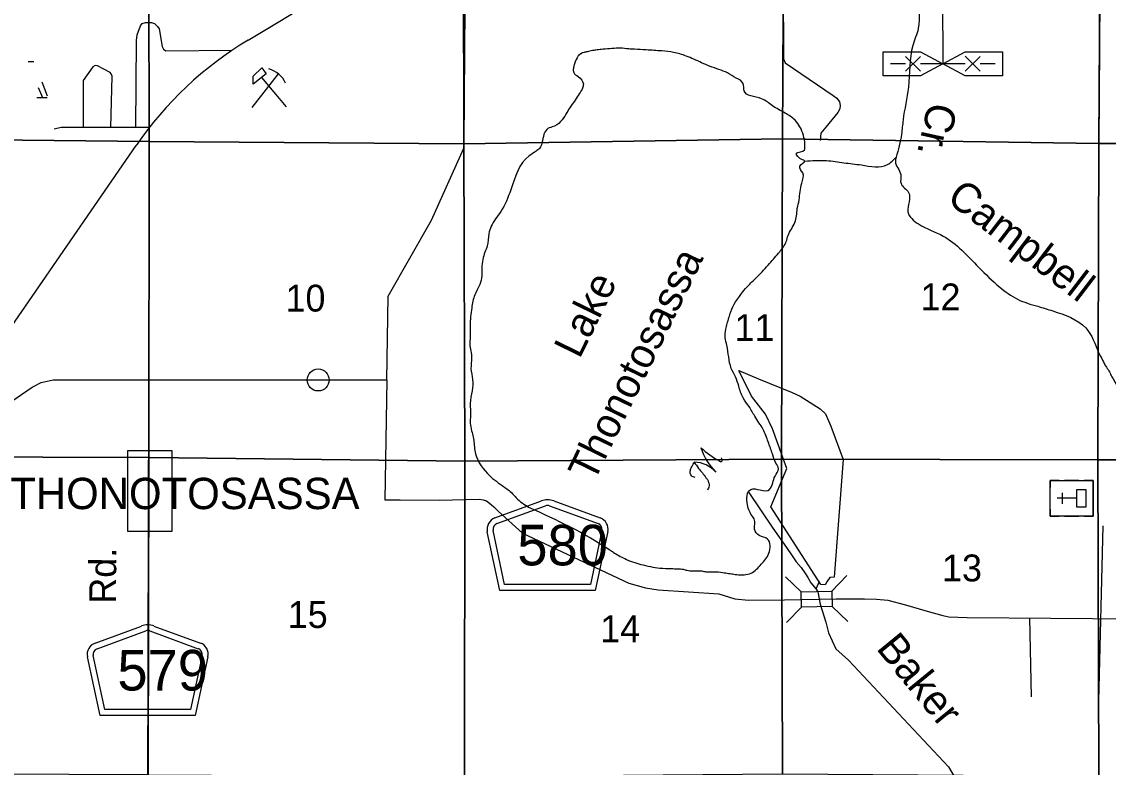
# Model space of a CAD drawing. Extents: x 380424 to 701066, y 1117407 to 1412949.
# Drawn here: x 556420 to 574618, y 1347425 to 1359908 of the extents above; entities that cross this region are included whole.
import ezdxf

# ---------------------------------------------------------------- set-up
doc = ezdxf.new("R2010")
doc.units = 0
for name, color, linetype in [('Bridges and Drawbridges County Highways', 7, 'Continuous'), ('Communities Names with Post Office', 7, 'Continuous'), ('County Roads Related Text', 7, 'Continuous'), ('County Routes Highway Center Lines', 7, 'Continuous'), ('Culture', 7, 'Continuous'), ('Lakes and Ponds', 7, 'Continuous'), ('Lakes and Ponds Text', 7, 'Continuous'), ('Local Roads Improved', 7, 'Continuous'), ('Local Roads Paved', 7, 'Continuous'), ('Local Roads Related Cells', 7, 'Continuous'), ('Masks for Text', 7, 'Continuous'), ('Narrow Canals', 7, 'Continuous'), ('Narrow River Creek and Branch and Slough', 7, 'Continuous'), ('Narrow River Creek and Branch and Slough Text', 7, 'Continuous'), ('Roadshields County Roads', 7, 'Continuous'), ('Section Lines', 7, 'Continuous'), ('Section Numbers', 7, 'Continuous'), ('Swamps', 7, 'Continuous'), ('Town Centers', 7, 'Continuous'), ('Township  and Range lines', 7, 'Continuous'), ('US Routes Highway Center Lines', 7, 'Continuous'), ('Wide Rivers and Canals Text', 7, 'Continuous')]:
    doc.layers.add(name, color=color, linetype=linetype)

msp = doc.modelspace()

# ---------------------------------------------------------------- linework, layer by layer
at = {"layer": 'Bridges and Drawbridges County Highways'}
for p, q in [((569475, 1350364), (569213, 1350614)), ((569986, 1350374), (570237, 1350635)), ((569992, 1350118), (570253, 1349867)), ((569480, 1350108), (569229, 1349847))]:
    msp.add_line(p, q, dxfattribs=at)
msp.add_lwpolyline([(569475, 1350364), (569986, 1350374), (569992, 1350118), (569480, 1350108)], close=True, dxfattribs=at)
at = {"layer": 'County Routes Highway Center Lines'}
msp.add_line((558555, 1358137), (558465, 1326167), dxfattribs=at)
msp.add_lwpolyline([(562533, 1353909), (562500, 1351905), (562760, 1351905), (563413, 1351899), (564087, 1351912), (564146, 1351902), (564203, 1351884), (564254, 1351846), (564290, 1351821), (564327, 1351786), (564401, 1351713), (564804, 1351342), (566590, 1350510), (566869, 1350431), (567079, 1350396), (568093, 1350326), (568364, 1350247), (568592, 1350221), (569195, 1350230), (570060, 1350247), (570533, 1350247), (570734, 1350239), (570926, 1350221), (571223, 1350142), (571582, 1350037), (571844, 1349967), (571949, 1349941), (572255, 1349932), (577859, 1349889)], dxfattribs=at)
at = {"layer": 'Culture'}
for p, q in [((560281, 1358474), (560718, 1359033)), ((560438, 1358975), (560851, 1358482)), ((573643, 1352228), (573643, 1352108)), ((573793, 1352228), (573643, 1352228)), ((574123, 1352228), (573883, 1352228)), ((574363, 1352228), (574213, 1352228)), ((574363, 1351628), (574363, 1352228)), ((573643, 1351838), (573643, 1352018)), ((573853, 1351838), (573853, 1352018)), ((574093, 1351928), (573763, 1351928)), ((573643, 1351748), (573643, 1351628)), ((573643, 1351628), (573793, 1351628)), ((573883, 1351628), (574123, 1351628)), ((574213, 1351628), (574363, 1351628))]:
    msp.add_line(p, q, dxfattribs=at)
for points in [[(560443, 1359134), (560513, 1359035), (560298, 1358863), (560298, 1358998)], [(573643, 1351628), (573643, 1352228), (574363, 1352228), (574363, 1351628)], [(574093, 1351778), (574093, 1352078), (574243, 1352078), (574243, 1351778)]]:
    msp.add_lwpolyline(points, close=True, dxfattribs=at)
msp.add_arc((560447, 1358701), 431, 24.5404, 74.8293, dxfattribs=at)
at = {"layer": 'Lakes and Ponds'}
msp.add_line((569408, 1356779), (569408, 1356782), dxfattribs=at)
msp.add_lwpolyline([(568430, 1354069), (568758, 1353927), (569324, 1353702), (569459, 1353637), (569793, 1353425), (569883, 1353341), (569973, 1353136), (570179, 1352576), (570024, 1350609), (569954, 1350603), (569902, 1350532), (569877, 1350481), (569806, 1350487), (568964, 1351786), (569234, 1352429), (568996, 1353092), (568874, 1353336), (568642, 1353638)], close=True, dxfattribs=at)
for centre, radius, start, end in [((568775, 1353091), 1029, 197.8123, 224.9499), ((568866, 1353931), 1575, 227.1631, 241.0317), ((567675, 1352045), 489, 40.6586, 89.0894)]:
    msp.add_arc(centre, radius, start, end, dxfattribs=at)
for points in [[(569408, 1356782), (569439, 1356924), (569457, 1357063), (569485, 1357205), (569500, 1357380), (569451, 1357489), (569531, 1357581), (569494, 1357597), (569395, 1357705), (569531, 1357761), (569537, 1357816), (569536, 1357858), (569454, 1358146), (569372, 1358259), (569204, 1358378), (568993, 1358502), (568811, 1358619), (568518, 1358752), (568502, 1358876), (568388, 1358965), (568239, 1359052), (567949, 1359160), (567807, 1359222), (567547, 1359333), (567337, 1359395), (567142, 1359419), (566876, 1359435), (566682, 1359447), (566586, 1359453), (566444, 1359466), (566305, 1359460), (566156, 1359447), (566057, 1359435), (565980, 1359425), (565893, 1359405), (565838, 1359395), (565741, 1359335), (565679, 1359204), (565659, 1359124), (565665, 1359057), (565739, 1358990), (565826, 1358862), (565811, 1358793), (565757, 1358702), (565688, 1358596), (565594, 1358460), (565535, 1358362), (565445, 1358236), (565303, 1358146), (565255, 1358132), (565181, 1358058), (565091, 1357787), (565034, 1357739), (564916, 1357660), (564611, 1357092)], [(564611, 1357092), (564442, 1356728), (564281, 1356483), (564243, 1356356), (564215, 1356153), (564178, 1356052), (564141, 1355926), (564125, 1355783), (564120, 1355614), (564078, 1355477), (564009, 1355335), (563956, 1355118), (563930, 1354823), (563930, 1354621), (563924, 1354513), (563955, 1354277), (563943, 1354104), (563972, 1353915), (563962, 1353730), (563930, 1353514), (563936, 1353394), (563933, 1353187), (563955, 1353059), (563997, 1352848), (564009, 1352727), (564218, 1352345), (564467, 1352142), (564620, 1352024), (564702, 1351934), (564910, 1351780)], [(564910, 1351780), (566271, 1351063), (566326, 1351026), (566518, 1350918), (566790, 1350822), (567108, 1350760), (567300, 1350751), (567405, 1350748), (567495, 1350739), (567563, 1350723), (567658, 1350714), (567791, 1350714), (567865, 1350702), (567906, 1350698), (567952, 1350695), (567992, 1350698), (568060, 1350698), (568187, 1350683), (568283, 1350668), (568369, 1350655), (568394, 1350652), (568635, 1350674), (568805, 1350825), (568935, 1351008), (568910, 1351246), (568771, 1351308), (568694, 1351410), (568697, 1351490), (568686, 1351582), (568663, 1351619), (568573, 1351820), (568629, 1352077), (568944, 1352074), (568997, 1352188), (569037, 1352299), (569092, 1352424), (569052, 1352517), (568993, 1352671), (568922, 1352872), (568836, 1353083), (568696, 1353303), (568601, 1353466), (568501, 1353609), (568428, 1353808), (568375, 1353960), (568304, 1354104), (568230, 1354491), (568202, 1354617), (568212, 1354759), (568236, 1354855), (568295, 1355050), (568375, 1355217), (568440, 1355306), (568490, 1355378), (568595, 1355497), (568743, 1355642), (568944, 1355859), (569114, 1356056), (569225, 1356227), (569256, 1356329), (569367, 1356544), (569408, 1356779)], [(567698, 1352275), (567636, 1352306), (567615, 1352366), (567628, 1352426), (567655, 1352479), (567676, 1352518), (567683, 1352535)], [(567683, 1352535), (567757, 1352428), (567819, 1352353), (567880, 1352273), (567909, 1352231), (567925, 1352184), (567934, 1352135), (567921, 1352098), (567903, 1352062)], [(568103, 1352553), (568115, 1352547), (568125, 1352546), (568140, 1352546), (568147, 1352552), (568149, 1352564), (568149, 1352581), (568145, 1352591), (568138, 1352607)]]:
    msp.add_spline(points, degree=3, dxfattribs=at)
at = {"layer": 'Local Roads Improved'}
msp.add_line((574526, 1351468), (574452, 1348534), dxfattribs=at)
at = {"layer": 'Local Roads Paved'}
for p, q in [((571839, 1360521), (571848, 1359203)), ((573296, 1349924), (573327, 1348604))]:
    msp.add_line(p, q, dxfattribs=at)
for points in [[(562533, 1353909), (562556, 1355313), (563285, 1356583), (563825, 1357789), (563823, 1358204), (563819, 1360560)], [(569170, 1360534), (569176, 1359287), (569206, 1359222), (570010, 1358672), (570069, 1358630), (570117, 1358565), (570129, 1358506), (570123, 1358447), (570087, 1358387), (569886, 1358145), (569803, 1358044), (569791, 1357920)], [(558331, 1358138), (558341, 1359596), (558355, 1359690), (558411, 1359840), (558439, 1359878), (558495, 1359896), (558594, 1359896), (558645, 1359878), (558692, 1359826), (558720, 1359789), (558772, 1359493), (558795, 1359446), (558833, 1359423), (559944, 1359430)], [(557914, 1358138), (557933, 1358996), (557919, 1359033), (557900, 1359057), (557689, 1359170), (557647, 1359174), (557609, 1359151), (557450, 1358926), (557450, 1358138)], [(558556, 1358138), (557080, 1358138), (556962, 1358110)], [(544188, 1345446), (544892, 1345923), (550487, 1349771), (553862, 1352084), (554602, 1352584), (554662, 1352609), (554792, 1352609), (554967, 1352669), (556327, 1353605), (556597, 1353790), (556747, 1353865), (556946, 1353910), (561568, 1353911), (562533, 1353912)]]:
    msp.add_lwpolyline(points, dxfattribs=at)
at = {"layer": 'Local Roads Related Cells'}
for p, q in [((570848, 1359403), (571473, 1359403)), ((570848, 1359003), (570848, 1359403)), ((571473, 1359403), (571848, 1359203)), ((571848, 1359203), (572223, 1359403)), ((572223, 1359403), (572848, 1359403)), ((572848, 1359403), (572848, 1359003)), ((571223, 1359078), (571473, 1359328)), ((571473, 1359078), (571223, 1359328)), ((572473, 1359080), (572223, 1359330)), ((572223, 1359078), (572473, 1359328)), ((571223, 1359203), (570973, 1359203)), ((571848, 1359203), (571473, 1359003)), ((572223, 1359203), (571473, 1359203)), ((572223, 1359003), (571848, 1359203)), ((572723, 1359203), (572473, 1359203)), ((571473, 1359003), (570848, 1359003)), ((572848, 1359003), (572223, 1359003))]:
    msp.add_line(p, q, dxfattribs=at)
at = {"layer": 'Masks for Text'}
msp.add_lwpolyline([(558194, 1352727), (558932, 1352727), (558932, 1351374), (558194, 1351374)], close=True, dxfattribs=at)
at = {"layer": 'Narrow Canals'}
msp.add_lwpolyline([(568598, 1352024), (568998, 1351430), (569228, 1351104), (569324, 1350963), (569391, 1350867), (569472, 1350771), (569548, 1350665), (569585, 1350601), (569635, 1350515), (569724, 1350404), (569754, 1350364), (569791, 1350157), (569887, 1349853), (569931, 1349675), (570057, 1349409), (570265, 1349216), (571942, 1347433), (572037, 1347270)], dxfattribs=at)
at = {"layer": 'Narrow River Creek and Branch and Slough'}
for points in [[(571389, 1360379), (571434, 1359794), (571344, 1359509), (571270, 1358812), (571181, 1358263), (571154, 1358026), (571064, 1357638)], [(569535, 1357574), (569900, 1357583), (570189, 1357547), (570483, 1357510), (570920, 1357517), (571065, 1357642)], [(571064, 1357638), (571052, 1357566), (571141, 1357350), (571147, 1357197), (571274, 1357051), (571262, 1356725), (571438, 1356523), (571855, 1356319), (572446, 1355797), (572800, 1355466), (573096, 1355262), (573436, 1355143), (573687, 1355066), (574240, 1354781), (574458, 1354354)], [(574458, 1354354), (574493, 1354298), (574550, 1354188), (574588, 1354122), (574637, 1354044), (574657, 1354004), (574700, 1353926), (574962, 1353454), (575008, 1353356), (575027, 1353283), (575096, 1353029), (575143, 1352829), (575180, 1352755), (575233, 1352613), (575252, 1352459), (575474, 1352081), (575683, 1352002)]]:
    msp.add_spline(points, degree=3, dxfattribs=at)
at = {"layer": 'Roadshields County Roads'}
for p, q in [((564344, 1351599), (565123, 1351885)), ((564378, 1351505), (565192, 1351804)), ((565261, 1351804), (566073, 1351506)), ((565330, 1351885), (566108, 1351599)), ((564508, 1350487), (564315, 1351390)), ((566137, 1351391), (565943, 1350487)), ((564427, 1350387), (564217, 1351369)), ((566234, 1351370), (566024, 1350387)), ((565943, 1350487), (564508, 1350487)), ((566024, 1350387), (564427, 1350387)), ((557647, 1349504), (558427, 1349790)), ((558634, 1349790), (559412, 1349504)), ((557682, 1349410), (558496, 1349709)), ((558565, 1349709), (559377, 1349410)), ((557731, 1348292), (557521, 1349274)), ((557812, 1348392), (557618, 1349295)), ((559440, 1349296), (559247, 1348392)), ((559538, 1349275), (559327, 1348292)), ((559327, 1348292), (557731, 1348292)), ((559247, 1348392), (557812, 1348392))]:
    msp.add_line(p, q, dxfattribs=at)
for centre, radius, start, end in [((565226, 1351604), 300, 69.8262, 110.1722), ((565226, 1351710), 100, 69.8262, 110.1722), ((564413, 1351411), 200, 110.1722, 192.0991), ((566039, 1351412), 200, 347.8993, 69.8262), ((564413, 1351411), 100, 110.1722, 192.0991), ((566039, 1351412), 100, 347.8993, 69.8262), ((558530, 1349509), 300, 69.8264, 110.1725), ((558530, 1349615), 100, 69.8265, 110.1725), ((557716, 1349316), 200, 110.1725, 192.0994), ((557716, 1349316), 100, 110.1725, 192.0994), ((559343, 1349317), 100, 347.8996, 69.8265), ((559343, 1349317), 200, 347.8996, 69.8265)]:
    msp.add_arc(centre, radius, start, end, dxfattribs=at)
at = {"layer": 'Section Lines'}
for points in [[(558542, 1363220), (558555, 1357902), (553243, 1357961), (553244, 1357982), (553132, 1363292), (553159, 1363292)], [(563866, 1363212), (563865, 1363205), (563826, 1357878), (563826, 1357861), (558555, 1357902), (558542, 1363220)], [(569189, 1363186), (569160, 1357955), (569160, 1357945), (563826, 1357861), (563826, 1357878), (563865, 1363205), (563866, 1363212), (563873, 1363212)], [(574493, 1363145), (574460, 1357872), (569160, 1357945), (569160, 1357955), (569189, 1363186)], [(579790, 1363121), (579826, 1357837), (579821, 1357838), (575614, 1357867), (574460, 1357872), (574493, 1363145), (575625, 1363139)], [(558555, 1357902), (558556, 1357891), (558547, 1352610), (553210, 1352626), (553205, 1352626), (553243, 1357961)], [(569160, 1357945), (569146, 1352599), (569146, 1352583), (563840, 1352552), (563826, 1357861)], [(574460, 1357872), (574444, 1352573), (574431, 1352573), (569160, 1352583), (569146, 1352583), (569146, 1352599), (569160, 1357945)], [(563826, 1357861), (563840, 1352552), (558567, 1352610), (558547, 1352610), (558556, 1357891), (558555, 1357902)], [(579826, 1357837), (579848, 1352545), (579838, 1352545), (575603, 1352570), (574444, 1352573), (574460, 1357872), (575614, 1357867), (579821, 1357838)], [(558547, 1352610), (558547, 1352601), (558536, 1347295), (558524, 1347296), (553243, 1347318), (553205, 1352614), (553205, 1352626), (553210, 1352626)], [(563840, 1352552), (563835, 1347274), (563835, 1347263), (563828, 1347263), (558536, 1347295), (558547, 1352601), (558547, 1352610), (558567, 1352610)], [(569146, 1352583), (569163, 1347311), (569158, 1347311), (563835, 1347263), (563835, 1347274), (563840, 1352552)], [(574444, 1352573), (574462, 1347269), (569163, 1347311), (569146, 1352583), (569160, 1352583), (574431, 1352573)], [(579848, 1352545), (579835, 1347220), (575594, 1347253), (574462, 1347269), (574444, 1352573), (575603, 1352570), (579838, 1352545)]]:
    msp.add_lwpolyline(points, close=True, dxfattribs=at)
at = {"layer": 'Swamps'}
msp.add_line((556694, 1358807), (556765, 1358641), dxfattribs=at)
for points in [[(556525, 1359241), (556624, 1359241)], [(556755, 1358903), (556847, 1358668)], [(556675, 1358641), (556845, 1358641)]]:
    msp.add_lwpolyline(points, dxfattribs=at)
at = {"layer": 'Town Centers'}
msp.add_circle((561385, 1353910), 184, dxfattribs=at)
at = {"layer": 'Township  and Range lines'}
for p, q in [((574493, 1363145), (574460, 1357872)), ((574460, 1357872), (574444, 1352573)), ((574444, 1352573), (574462, 1347269))]:
    msp.add_line(p, q, dxfattribs=at)
at = {"layer": 'US Routes Highway Center Lines'}
for p, q in [((560213, 1359602), (563282, 1361447)), ((555992, 1354438), (558334, 1357836))]:
    msp.add_line(p, q, dxfattribs=at)
msp.add_arc((563357, 1354374), 6100, 121.0222, 145.4239, dxfattribs=at)
at = {"layer": 'Wide Rivers and Canals Text'}
msp.add_line((569775, 1350535), (569721, 1350408), dxfattribs=at)

# ---------------------------------------------------------------- texts
at = {"layer": 'Communities Names with Post Office'}
msp.add_text('THONOTOSASSA', height=525, rotation=0.0003, dxfattribs=at).set_placement((556227, 1351747))
at = {"layer": 'County Roads Related Text'}
msp.add_text('Rd.', height=450, rotation=89.8371, dxfattribs=at).set_placement((558000, 1350163))
at = {"layer": 'Lakes and Ponds Text'}
for s, p in [('Thonotosassa', (566001, 1352179)), ('Lake', (565763, 1354249))]:
    msp.add_text(s, height=500, rotation=63.9617, dxfattribs=at).set_placement(p)
at = {"layer": 'Narrow River Creek and Branch and Slough Text'}
for s, rotation, p in [('Cr.', 257.6235, (571605, 1358579)), ('Campbell', 322.5631, (571889, 1356909)), ('Baker', 309.2895, (570718, 1349413))]:
    msp.add_text(s, height=500, rotation=rotation, dxfattribs=at).set_placement(p)
at = {"layer": 'Roadshields County Roads'}
for s, rotation, p in [('580', 359.9992, (564720, 1350805)), ('579', 359.9995, (558022, 1348710))]:
    msp.add_text(s, height=680, rotation=rotation, dxfattribs=at).set_placement(p)
at = {"layer": 'Section Numbers'}
for s, p in [('10', (560837, 1355055)), ('12', (571473, 1355075)), ('11', (568357, 1354561)), ('13', (571833, 1350537)), ('15', (560875, 1349757)), ('14', (566107, 1349519))]:
    msp.add_text(s, height=450, dxfattribs=at).set_placement(p)

doc.saveas('drawing.dxf')
